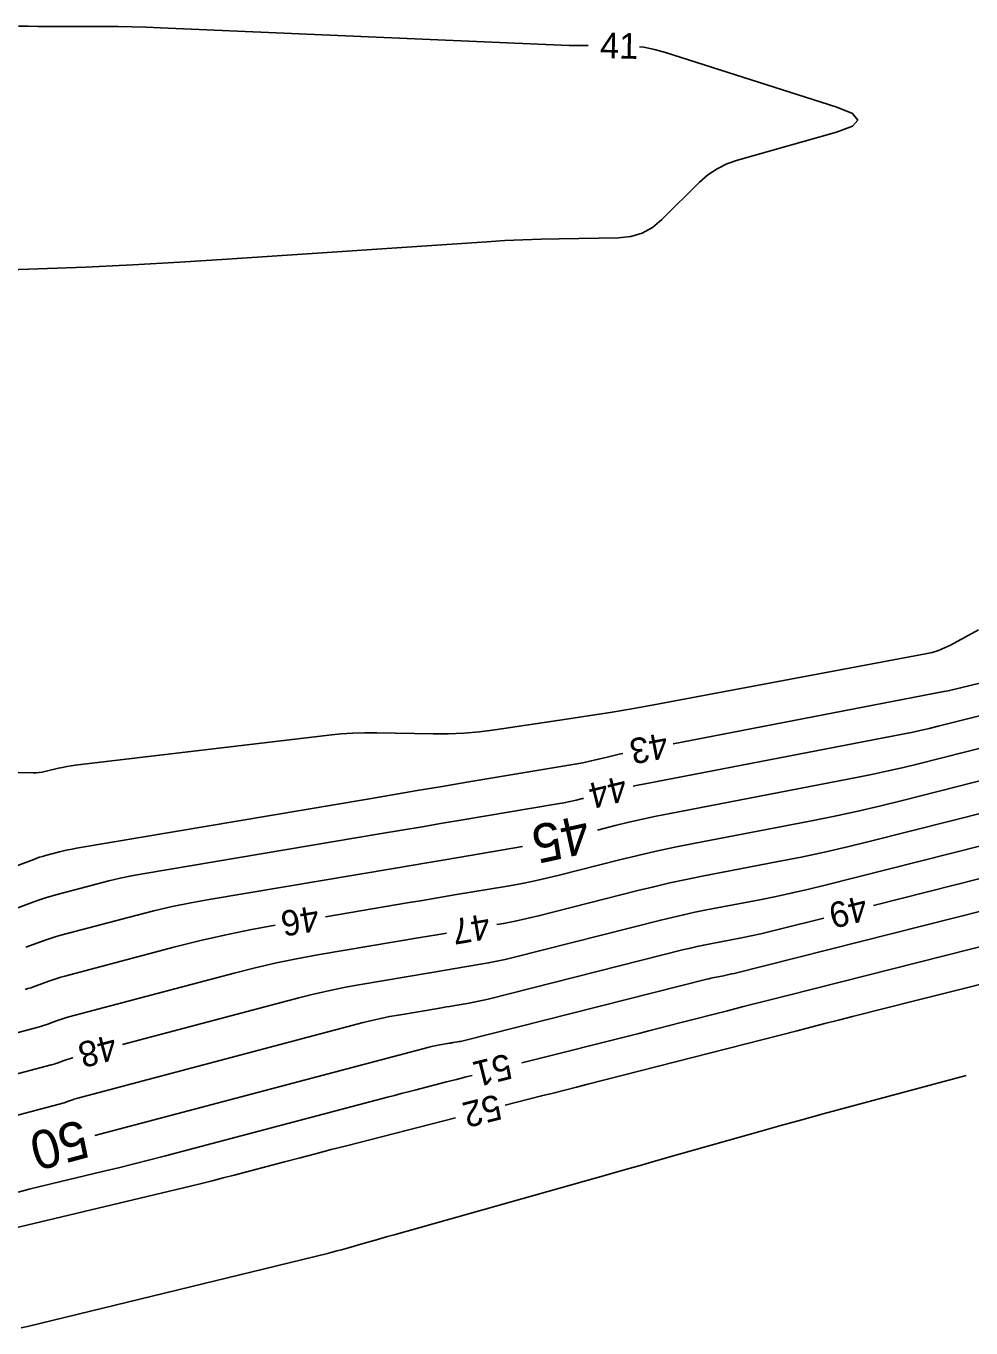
# Model space of a CAD drawing. Extents: x 2384780 to 2405861, y 547869 to 573706.
# Drawn here: x 2390271.7 to 2390345.6, y 552545.6 to 552647.4 of the extents above; entities that cross this region are included whole.
import ezdxf

# ---------------------------------------------------------------- set-up
doc = ezdxf.new("R2010")
doc.units = 0
doc.layers.add('Old_Level_60', color=7, linetype='Continuous')
doc.layers.add('Old_Level_61', color=7, linetype='Continuous')

msp = doc.modelspace()

# ---------------------------------------------------------------- linework, layer by layer
at = {"layer": 'Old_Level_60'}
for points in [[(2390315.645, 552645.84975), (2390315.37875, 552645.84975), (2390314.7645, 552645.853), (2390314.1505, 552645.863), (2390313.53675, 552645.88), (2390312.923, 552645.90325), (2390282.201, 552647.2475), (2390281.1005, 552647.2895), (2390279.9995, 552647.31975), (2390278.89825, 552647.33775), (2390277.797, 552647.34375), (2390274.1985, 552647.34375), (2390273.42725, 552647.34575), (2390272.65625, 552647.352), (2390271.88525, 552647.36225), (2390271.1145, 552647.37675)], [(2390257.61625, 552627.882), (2390272.6475, 552628.39075), (2390276.3445, 552628.5315), (2390280.03975, 552628.7035), (2390283.7335, 552628.9065), (2390287.4255, 552629.14075), (2390307.707, 552630.5135), (2390309.1235, 552630.6), (2390310.5405, 552630.66775), (2390311.9585, 552630.71675), (2390313.37725, 552630.74675), (2390318.01325, 552630.81475), (2390318.9705, 552630.915), (2390319.85575, 552631.18675), (2390320.669, 552631.62975), (2390321.41, 552632.24425), (2390324.34775, 552635.16175), (2390325.00525, 552635.73875), (2390325.719, 552636.2195), (2390326.48875, 552636.60425), (2390327.31475, 552636.8925), (2390335.04575, 552639.06775), (2390336.29025, 552639.541), (2390336.71075, 552640.02825), (2390336.30725, 552640.5295), (2390335.0795, 552641.045), (2390321.672, 552645.317), (2390320.83075, 552645.55), (2390319.97925, 552645.7165), (2390319.64075, 552645.75575)], [(2390346.14025, 552600.1595), (2390343.97275, 552598.9805), (2390343.5015, 552598.74725), (2390343.01625, 552598.553), (2390342.51725, 552598.3975), (2390342.0045, 552598.281), (2390320.76625, 552594.31225), (2390319.06225, 552594.00225), (2390317.3555, 552593.70825), (2390315.646, 552593.43075), (2390313.93375, 552593.16925), (2390308.336, 552592.342), (2390307.13475, 552592.18975), (2390305.9305, 552592.08775), (2390304.723, 552592.03625), (2390303.51225, 552592.03475), (2390299.118, 552592.12075), (2390298.17725, 552592.12275), (2390297.238, 552592.0925), (2390296.3005, 552592.02975), (2390295.3645, 552591.9345), (2390275.54925, 552589.57275), (2390275.21875, 552589.52875), (2390274.89, 552589.47525), (2390274.56275, 552589.4125), (2390274.237, 552589.34075), (2390273.176, 552589.0905), (2390272.948, 552589.04425), (2390272.71825, 552589.0125), (2390272.487, 552588.99525), (2390272.25425, 552588.99275), (2390262.81625, 552589.1835)], [(2390346.264, 552596.00825), (2390344.74875, 552595.6255), (2390344.4235, 552595.54575), (2390344.09725, 552595.47075), (2390343.77, 552595.40025), (2390343.44175, 552595.3345), (2390322.2715, 552591.25375)], [(2390346.228, 552593.44975), (2390342.99125, 552592.632), (2390342.29675, 552592.46175), (2390341.59975, 552592.3015), (2390340.90075, 552592.15125), (2390340.1995, 552592.01075), (2390320.21325, 552588.158), (2390319.51725, 552588.01875), (2390319.1525, 552587.94025)], [(2390318.34375, 552590.49625), (2390318.0715, 552590.44175), (2390317.755, 552590.3735), (2390317.4395, 552590.301), (2390317.125, 552590.224), (2390316.0995, 552589.96475), (2390315.87925, 552589.9115), (2390315.65825, 552589.8625), (2390315.436, 552589.81825), (2390315.213, 552589.77825), (2390306.16, 552588.248), (2390304.22, 552587.92), (2390302.28, 552587.59225), (2390300.34025, 552587.26425), (2390298.40025, 552586.9365), (2390275.6445, 552583.09025), (2390275.30725, 552583.02925), (2390274.97175, 552582.96075), (2390274.63775, 552582.8845), (2390274.30525, 552582.8005), (2390273.2225, 552582.51375), (2390272.9915, 552582.44925), (2390272.762, 552582.3795), (2390272.5345, 552582.304), (2390272.30875, 552582.22275), (2390269.6165, 552581.2165)], [(2390348.60475, 552588.9515), (2390340.21125, 552586.83075), (2390338.40975, 552586.38925), (2390336.6025, 552585.9735), (2390334.7895, 552585.58375), (2390332.97075, 552585.21975), (2390323.86225, 552583.46375), (2390322.409, 552583.173), (2390320.9605, 552582.86125), (2390319.5165, 552582.52925), (2390318.077, 552582.17625), (2390313.3825, 552580.99), (2390312.37425, 552580.74575), (2390311.362, 552580.52225), (2390310.34525, 552580.31875), (2390309.32425, 552580.13575), (2390305.19175, 552579.43725), (2390304.306, 552579.2875), (2390303.4205, 552579.13775), (2390302.535, 552578.988), (2390301.6495, 552578.8385), (2390295.11, 552577.733)], [(2390315.267, 552586.9915), (2390315.19375, 552586.97325), (2390314.711, 552586.85625), (2390314.226, 552586.749), (2390313.73925, 552586.65175), (2390313.25025, 552586.564), (2390305.83725, 552585.311), (2390304.24875, 552585.0425), (2390302.66025, 552584.774), (2390301.07175, 552584.5055), (2390299.48325, 552584.237), (2390280.82925, 552581.08425), (2390279.9385, 552580.92325), (2390279.052, 552580.74175), (2390278.16975, 552580.54025), (2390277.292, 552580.3185), (2390274.1255, 552579.48), (2390273.6675, 552579.3525), (2390273.21325, 552579.214), (2390272.7625, 552579.06425), (2390272.31525, 552578.9035), (2390270.86, 552578.35975)], [(2390349.995, 552586.75325), (2390337.70325, 552583.64775), (2390335.90825, 552583.20775), (2390334.10725, 552582.7935), (2390332.30075, 552582.405), (2390330.48825, 552582.04225), (2390324.55875, 552580.89925), (2390323.29, 552580.64525), (2390322.02525, 552580.37325), (2390320.76475, 552580.08325), (2390319.50825, 552579.77525), (2390311.75175, 552577.815), (2390310.84425, 552577.5955), (2390309.933, 552577.394), (2390309.01775, 552577.211), (2390308.51225, 552577.12025)], [(2390351.3855, 552584.55525), (2390334.15325, 552580.2015), (2390332.8865, 552579.891), (2390331.6155, 552579.5985), (2390330.3405, 552579.3245), (2390329.0615, 552579.0685), (2390324.87675, 552578.26175), (2390323.9815, 552578.0825), (2390323.089, 552577.8905), (2390322.1995, 552577.686), (2390321.31275, 552577.4685), (2390309.788, 552574.556), (2390309.148, 552574.40125), (2390308.5055, 552574.25925), (2390307.86, 552574.13), (2390307.21175, 552574.01375), (2390305.09025, 552573.65525), (2390304.6355, 552573.57825), (2390304.18075, 552573.5015), (2390303.72625, 552573.42475), (2390303.2715, 552573.34775), (2390297.721, 552572.40975), (2390296.5345, 552572.19525), (2390295.354, 552571.95375), (2390294.17925, 552571.68525), (2390293.01025, 552571.39), (2390279.23225, 552567.741)], [(2390352.77575, 552582.357), (2390337.93475, 552578.6075)], [(2390334.0565, 552577.6275), (2390330.60325, 552576.755), (2390329.8645, 552576.574), (2390329.12375, 552576.40375), (2390328.3805, 552576.24375), (2390327.63475, 552576.0945), (2390325.195, 552575.62425), (2390324.67325, 552575.51975), (2390324.15275, 552575.408), (2390323.63425, 552575.2885), (2390323.11725, 552575.16175), (2390307.82425, 552571.297), (2390307.45175, 552571.207), (2390307.07775, 552571.12425), (2390306.70225, 552571.049), (2390306.325, 552570.9815), (2390305.09025, 552570.77275), (2390304.8255, 552570.728), (2390304.561, 552570.68325), (2390304.2965, 552570.6385), (2390304.03175, 552570.594), (2390300.8015, 552570.048), (2390300.111, 552569.923), (2390299.424, 552569.7825), (2390298.74025, 552569.62625), (2390298.05975, 552569.4545), (2390275.637, 552563.51575), (2390275.541, 552563.489), (2390275.44575, 552563.46), (2390275.351, 552563.42875), (2390275.25725, 552563.395), (2390274.952, 552563.28075), (2390274.88625, 552563.25725), (2390274.82, 552563.23525), (2390274.75325, 552563.21475), (2390274.686, 552563.19625), (2390264.1175, 552560.39825)], [(2390304.569, 552576.4495), (2390304.4455, 552576.4285), (2390303.80075, 552576.3195), (2390303.156, 552576.21075), (2390302.51125, 552576.10175), (2390294.64075, 552574.7715), (2390292.95825, 552574.46725), (2390291.284, 552574.12475), (2390289.61825, 552573.74425), (2390287.9605, 552573.3255), (2390275.0325, 552569.9015), (2390274.79175, 552569.8345), (2390274.55275, 552569.76175), (2390274.31575, 552569.683), (2390274.0805, 552569.59825), (2390273.31525, 552569.31225), (2390273.1505, 552569.25325), (2390272.9845, 552569.198), (2390272.81725, 552569.147), (2390272.64875, 552569.10025), (2390266.9645, 552567.59525)], [(2390291.166, 552577.066), (2390289.20075, 552576.71075), (2390287.21225, 552576.30425), (2390285.234, 552575.85225), (2390283.26525, 552575.35475), (2390274.73025, 552573.09425), (2390274.417, 552573.00725), (2390274.10625, 552572.9125), (2390273.798, 552572.81), (2390273.492, 552572.7), (2390272.49675, 552572.328), (2390272.28275, 552572.251), (2390272.06675, 552572.1795), (2390271.84925, 552572.11325), (2390271.63, 552572.05225)], [(2390349.74425, 552576.26225), (2390331.1215, 552571.555), (2390329.9755, 552571.265), (2390328.83, 552570.974), (2390327.6845, 552570.68225), (2390326.5395, 552570.3895), (2390322.79875, 552569.43225), (2390321.99725, 552569.2275), (2390321.1955, 552569.02325), (2390320.3935, 552568.81975), (2390319.5915, 552568.6165), (2390310.4515, 552566.30625)], [(2390349.516, 552573.283), (2390345.11725, 552572.16075), (2390344.1745, 552571.9205), (2390343.23175, 552571.681), (2390342.28875, 552571.44175), (2390341.34575, 552571.203), (2390336.2935, 552569.926), (2390335.211, 552569.652), (2390334.12875, 552569.37725), (2390333.0465, 552569.1015), (2390331.9645, 552568.825), (2390315.6255, 552564.64375), (2390314.719, 552564.412), (2390313.8125, 552564.18125), (2390312.90575, 552563.951), (2390311.99875, 552563.72125), (2390309.1575, 552563.003)], [(2390275.36575, 552566.71675), (2390275.33475, 552566.70875), (2390275.16625, 552566.66175), (2390274.99925, 552566.61075), (2390274.83325, 552566.55575), (2390274.66875, 552566.4965), (2390274.1335, 552566.2965), (2390274.0185, 552566.25525), (2390273.90225, 552566.2165), (2390273.78525, 552566.181), (2390273.6675, 552566.14825), (2390266.19775, 552564.17075)], [(2390306.57375, 552565.3255), (2390306.102, 552565.2055), (2390305.34, 552565.0115), (2390304.57825, 552564.81675), (2390302.09025, 552564.18), (2390301.557, 552564.043), (2390301.02425, 552563.905), (2390300.49175, 552563.766), (2390299.9595, 552563.626), (2390282.59775, 552559.041), (2390281.3725, 552558.7215), (2390280.14575, 552558.4095), (2390278.91675, 552558.105), (2390277.686, 552557.808), (2390273.6625, 552556.85025), (2390272.80075, 552556.6425), (2390271.9405, 552556.4295), (2390271.0815, 552556.2115)], [(2390345.1855, 552565.33125), (2390334.0035, 552562.31675), (2390332.3495, 552561.8675), (2390330.697, 552561.4125), (2390329.04625, 552560.95175), (2390327.39725, 552560.48475), (2390322.01275, 552558.94975), (2390320.85875, 552558.62125), (2390319.70475, 552558.2935), (2390318.5505, 552557.96675), (2390317.39575, 552557.6405), (2390300.47375, 552552.86575), (2390299.957, 552552.71975), (2390299.44, 552552.57325), (2390298.92325, 552552.42675), (2390298.40675, 552552.27975), (2390296.719, 552551.79925), (2390296.357, 552551.698), (2390295.994, 552551.60025), (2390295.63, 552551.506), (2390295.26525, 552551.41525), (2390271.804, 552545.6935), (2390271.31575, 552545.5815)], [(2390305.28125, 552562.0155), (2390296.7585, 552559.83375), (2390295.546, 552559.52225), (2390294.334, 552559.20825), (2390293.1225, 552558.892), (2390291.91175, 552558.5735), (2390287.9575, 552557.52925), (2390287.1095, 552557.30825), (2390286.26025, 552557.09225), (2390285.4095, 552556.8815), (2390284.55775, 552556.676), (2390267.25375, 552552.55675)]]:
    msp.add_lwpolyline(points, dxfattribs=at)
at = {"layer": 'Old_Level_61'}
for points in [[(2390346.90275, 552591.071), (2390341.44725, 552589.6925), (2390340.27625, 552589.4055), (2390339.1015, 552589.13525), (2390337.92325, 552588.882), (2390336.741, 552588.64525), (2390322.03775, 552585.811), (2390320.96325, 552585.59575), (2390319.892, 552585.3655), (2390318.824, 552585.11975), (2390317.75975, 552584.85875), (2390316.37025, 552584.50775)], [(2390310.51325, 552583.219), (2390305.5145, 552582.374), (2390304.2775, 552582.165), (2390303.0405, 552581.956), (2390301.80325, 552581.74675), (2390300.56625, 552581.53775), (2390286.014, 552579.07825), (2390284.5695, 552578.817), (2390283.132, 552578.523), (2390281.70175, 552578.19625), (2390280.27875, 552577.83675), (2390274.42775, 552576.287), (2390274.04225, 552576.17975), (2390273.65975, 552576.06325), (2390273.28025, 552575.93725), (2390272.9035, 552575.80175), (2390271.6785, 552575.344)], [(2390354.16625, 552580.159), (2390327.053, 552573.30875), (2390326.84275, 552573.25725), (2390326.63175, 552573.20875), (2390326.42025, 552573.16325), (2390326.208, 552573.12075), (2390325.51325, 552572.98675), (2390325.36475, 552572.957), (2390325.2165, 552572.92525), (2390325.069, 552572.89125), (2390324.92175, 552572.85525), (2390305.8605, 552568.038), (2390305.7555, 552568.01275), (2390305.65025, 552567.9895), (2390305.5445, 552567.96825), (2390305.438, 552567.94925), (2390305.09025, 552567.89025), (2390305.01575, 552567.87775), (2390304.94125, 552567.86525), (2390304.8665, 552567.8525), (2390304.792, 552567.84), (2390303.882, 552567.68625), (2390303.6875, 552567.651), (2390303.49375, 552567.6115), (2390303.30125, 552567.5675), (2390303.1095, 552567.519), (2390277.0815, 552560.6255)]]:
    msp.add_lwpolyline(points, dxfattribs=at)

# ---------------------------------------------------------------- texts
at = {"layer": 'Old_Level_60'}
for s, rotation, p in [('41', 358.65285, (2390316.55125, 552644.875)), ('43', 190.9156694, (2390321.67225, 552592.15675)), ('44', 193.7202722, (2390318.40675, 552588.80425)), ('46', 189.5989056, (2390294.43075, 552578.63275)), ('49', 194.1792806, (2390337.18575, 552579.44975)), ('47', 189.653675, (2390307.786, 552578.009)), ('48', 194.8340722, (2390278.4965, 552568.5805)), ('51', 194.1948056, (2390309.3665, 552567.0635)), ('52', 194.2959139, (2390308.55125, 552563.8825))]:
    msp.add_text(s, height=2, rotation=rotation, dxfattribs=at).set_placement(p)
at = {"layer": 'Old_Level_61'}
for s, rotation, p in [('45', 192.4091333, (2390315.386, 552585.7425)), ('50', 194.9838667, (2390276.08, 552561.90175))]:
    msp.add_text(s, height=3, rotation=rotation, dxfattribs=at).set_placement(p)

doc.saveas('drawing.dxf')
